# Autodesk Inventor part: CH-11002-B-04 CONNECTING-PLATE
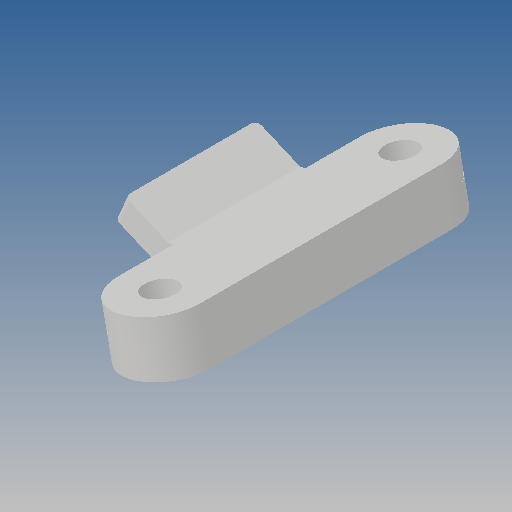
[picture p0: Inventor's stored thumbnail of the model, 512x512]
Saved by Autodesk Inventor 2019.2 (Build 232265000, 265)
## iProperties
Created: 2012-09
Part Number: CH-11002-B-04 CONNECTING-PLATE
Material: Ogólny
Document SubType Name: Modeling
Designer: CADENGINEERING4
Density: 1 g/cm^3
Appearance: Domyślna
Author: CADENGINEERING4
Revision Number: ÈÎºÎ
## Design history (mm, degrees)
feature "ÇÐ³ý-À­Éì2"
feature "¾µÏò1"
node "Bryła1"
node "Bryła2"
